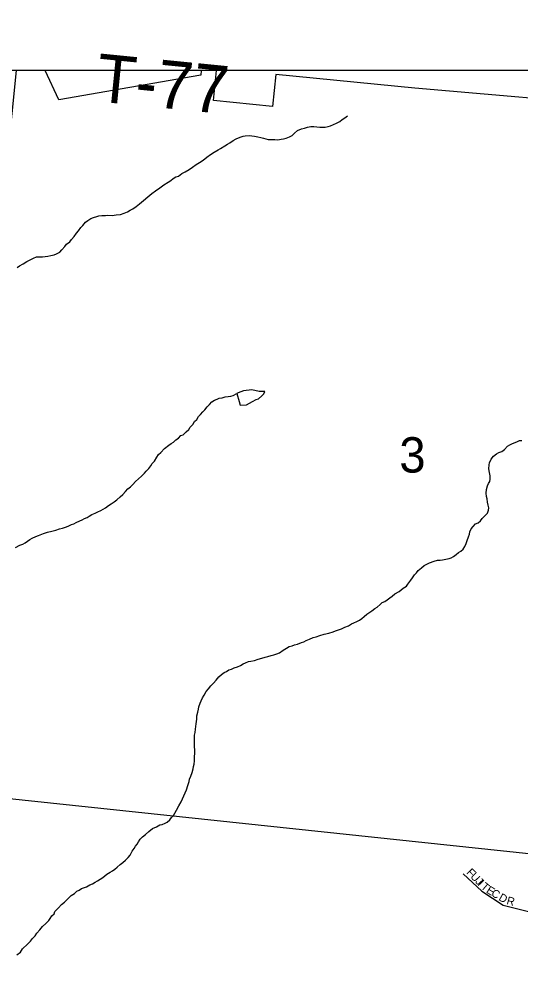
# Model space of a CAD drawing. Extents: x 0 to 34, y -4 to 22.
# Drawn here: x 5.062 to 5.48, y 18.636 to 19.435 of the extents above; entities that cross this region are included whole.
import ezdxf

# ---------------------------------------------------------------- set-up
doc = ezdxf.new("R2010")
doc.units = 0
for name, color, linetype in [('GM_X_City_Street', 7, 'Continuous'), ('GM_X_City_Street_Text', 7, 'Continuous'), ('GM_X_Corporation', 7, 'Continuous'), ('GM_X_Minor_Lake', 7, 'Continuous'), ('GM_X_Minor_River', 7, 'Continuous'), ('GM_X_Section', 7, 'Continuous'), ('GM_X_Section_Text', 7, 'Continuous'), ('GM_X_Township', 7, 'Continuous'), ('GM_X_Township_Road_Text', 7, 'Continuous'), ('SH_Text', 7, 'Continuous')]:
    doc.layers.add(name, color=color, linetype=linetype)

msp = doc.modelspace()

# ---------------------------------------------------------------- linework, layer by layer
at = {"layer": 'GM_X_City_Street'}
msp.add_lwpolyline([(5.43147, 18.72305), (5.44706, 18.70841), (5.46488, 18.69696), (5.4881, 18.69091), (5.51387, 18.68901), (5.5336, 18.68646), (5.54851, 18.68204)], dxfattribs=at)
at = {"layer": 'GM_X_Corporation'}
msp.add_lwpolyline([(5.57096, 19.36176), (5.39129, 19.37747), (5.27543, 19.38883), (5.27278, 19.3623), (5.22344, 19.36713), (5.22593, 19.39206), (5.21309, 19.39206), (5.213, 19.38827), (5.09474, 19.36784), (5.08313, 19.39206), (5.04556, 19.39206)], dxfattribs=at)
at = {"layer": 'GM_X_Minor_Lake'}
for points in [[(5.26638, 19.12474), (5.26156, 19.12486), (5.25543, 19.12607), (5.24844, 19.12544), (5.24411, 19.12367), (5.24303, 19.12316)], [(5.24303, 19.12316), (5.24474, 19.11643), (5.24574, 19.11346), (5.2511, 19.1136), (5.25599, 19.11643), (5.25898, 19.11796), (5.26087, 19.11872), (5.26387, 19.12105), (5.26553, 19.12289), (5.26638, 19.12474)]]:
    msp.add_lwpolyline(points, dxfattribs=at)
at = {"layer": 'GM_X_Minor_River'}
for points in [[(5.14901, 19.27327), (5.15173, 19.27452), (5.15418, 19.27578), (5.15637, 19.27705), (5.15911, 19.27883), (5.16186, 19.28115), (5.16517, 19.28399), (5.16875, 19.28682), (5.17205, 19.28965), (5.17508, 19.29196), (5.17865, 19.29452), (5.1822, 19.29682), (5.18576, 19.29911), (5.18796, 19.30065), (5.18988, 19.30219), (5.19207, 19.30346), (5.19423, 19.3042), (5.19698, 19.30625), (5.19998, 19.30776), (5.20326, 19.30979), (5.206, 19.31158), (5.20902, 19.31389), (5.21175, 19.31541), (5.21477, 19.31745), (5.2178, 19.32003), (5.22108, 19.32207), (5.2241, 19.32411), (5.22738, 19.32615), (5.22929, 19.32716), (5.23285, 19.32945), (5.23503, 19.33072), (5.23722, 19.33199), (5.23995, 19.33377), (5.24242, 19.3353), (5.24567, 19.33654), (5.24811, 19.33753), (5.25, 19.33774), (5.25322, 19.3379), (5.25536, 19.33784), (5.25776, 19.3375), (5.26042, 19.33688), (5.26281, 19.33627), (5.2652, 19.33566), (5.26706, 19.33534), (5.26892, 19.33475), (5.27186, 19.33466), (5.27454, 19.33458), (5.27695, 19.3345), (5.27991, 19.33494), (5.28179, 19.33515), (5.28396, 19.33589), (5.28667, 19.33687), (5.28913, 19.33813), (5.29106, 19.33994), (5.29355, 19.34227), (5.2968, 19.34351), (5.29924, 19.34423), (5.30194, 19.34495), (5.30464, 19.3454), (5.30705, 19.3456), (5.30945, 19.34525), (5.31212, 19.3449), (5.31399, 19.34485), (5.31641, 19.34504), (5.31911, 19.34549), (5.321, 19.34597), (5.32345, 19.34723), (5.32589, 19.34822), (5.32862, 19.34974), (5.33082, 19.35127), (5.33301, 19.35281), (5.33521, 19.35434)], [(5.05991, 19.22793), (5.06183, 19.22947), (5.06483, 19.23098), (5.06784, 19.23303), (5.0703, 19.23429), (5.07356, 19.23579), (5.07601, 19.23705), (5.07842, 19.23698), (5.0811, 19.23689), (5.08325, 19.2371), (5.08541, 19.23756), (5.0881, 19.23801), (5.0908, 19.23873), (5.0927, 19.23948), (5.09542, 19.24073), (5.0971, 19.24281), (5.09961, 19.24567), (5.10101, 19.2475), (5.10375, 19.24955), (5.10515, 19.25138), (5.10738, 19.25398), (5.10934, 19.25659), (5.11102, 19.25868), (5.11298, 19.26129), (5.11465, 19.26311), (5.11688, 19.26571), (5.1188, 19.26725), (5.12127, 19.26878), (5.12344, 19.26978), (5.12615, 19.2705), (5.12804, 19.27098), (5.13046, 19.27144), (5.13341, 19.27134), (5.13556, 19.27154), (5.13904, 19.27144), (5.14253, 19.27186), (5.14603, 19.27229), (5.14901, 19.27327)], [(5.05863, 18.99476), (5.06218, 18.99679), (5.06461, 18.99751), (5.06653, 18.99879), (5.06845, 19.00007), (5.07037, 19.00134), (5.07229, 19.00262), (5.07554, 19.00385), (5.07772, 19.00486), (5.08179, 19.0066), (5.08531, 19.00756), (5.08882, 19.00852), (5.09206, 19.00922), (5.09532, 19.01046), (5.09774, 19.01092), (5.101, 19.01215), (5.1029, 19.01289), (5.10507, 19.0139), (5.10724, 19.01463), (5.10915, 19.01564), (5.11214, 19.01688), (5.11405, 19.01789), (5.11596, 19.0189), (5.11813, 19.0199), (5.12004, 19.02091), (5.12223, 19.02218), (5.12495, 19.02343), (5.12712, 19.02444), (5.12958, 19.0257), (5.13149, 19.0267), (5.13339, 19.02771), (5.13614, 19.02977), (5.13833, 19.03104), (5.1408, 19.03283), (5.143, 19.03463), (5.14575, 19.03695), (5.14797, 19.03902), (5.15019, 19.04135), (5.15214, 19.0437), (5.15433, 19.04523), (5.15628, 19.04731), (5.1585, 19.04965), (5.16099, 19.05197), (5.16347, 19.0543), (5.16596, 19.05663), (5.16736, 19.05845), (5.16957, 19.06052), (5.17126, 19.06288), (5.17239, 19.06471), (5.17433, 19.06679), (5.17631, 19.06993), (5.17773, 19.07229), (5.17966, 19.07384), (5.18272, 19.07722), (5.18629, 19.08004), (5.18821, 19.08132), (5.19013, 19.0826), (5.19206, 19.08441), (5.19426, 19.08594), (5.1962, 19.08802), (5.1981, 19.08876), (5.20059, 19.09109), (5.2028, 19.09316), (5.20393, 19.09499), (5.20615, 19.09733), (5.20757, 19.09969), (5.20951, 19.1015), (5.21092, 19.10386), (5.21259, 19.10568), (5.21453, 19.10776), (5.2162, 19.10957), (5.21816, 19.11192), (5.2201, 19.114), (5.22204, 19.11607), (5.22424, 19.11761), (5.22641, 19.11834)], [(5.22641, 19.11834), (5.2283, 19.11908), (5.23073, 19.11954), (5.23317, 19.12027), (5.23558, 19.12046), (5.23801, 19.12092), (5.2399, 19.1214), (5.24303, 19.12316)], [(5.44185, 19.01446), (5.44403, 19.01546), (5.44596, 19.017), (5.44736, 19.01883), (5.44985, 19.02142), (5.4518, 19.0235), (5.45268, 19.02588), (5.45274, 19.02774), (5.45229, 19.03016), (5.45183, 19.03258), (5.45138, 19.03527), (5.45092, 19.03742), (5.45074, 19.0401), (5.45084, 19.04303), (5.45174, 19.04621), (5.45261, 19.04805), (5.45374, 19.04989), (5.45407, 19.05175), (5.45389, 19.05442), (5.45345, 19.05738), (5.45301, 19.06033), (5.45312, 19.06353), (5.45345, 19.06539), (5.45488, 19.06828), (5.45685, 19.07089), (5.45932, 19.07269), (5.46123, 19.07396), (5.46367, 19.07469), (5.46587, 19.07649), (5.46837, 19.07909), (5.47029, 19.08036), (5.47273, 19.08136), (5.47626, 19.08285), (5.47844, 19.08385), (5.48032, 19.08406)], [(5.21328, 18.8671), (5.21443, 18.86947), (5.21558, 18.87184), (5.21728, 18.87473), (5.21924, 18.87707), (5.2212, 18.87968), (5.22341, 18.88175), (5.22564, 18.88435), (5.22787, 18.88696), (5.23008, 18.88902), (5.23227, 18.89056), (5.23418, 18.89157), (5.23637, 18.89284), (5.23854, 18.89357), (5.24071, 18.89457), (5.24341, 18.89529), (5.24587, 18.89655), (5.24832, 18.89781), (5.25023, 18.89882), (5.25267, 18.89981), (5.25455, 18.90002), (5.25753, 18.90073), (5.26077, 18.9017), (5.26375, 18.90268), (5.26645, 18.9034), (5.26862, 18.90413), (5.27159, 18.90484), (5.27375, 18.90531), (5.2762, 18.9063), (5.27836, 18.90704), (5.28165, 18.90934), (5.28438, 18.91086), (5.28658, 18.91239), (5.289, 18.91285), (5.2909, 18.91359), (5.29334, 18.91432), (5.29686, 18.91555), (5.29876, 18.91629), (5.30067, 18.9173), (5.30339, 18.91855), (5.30665, 18.91979), (5.30908, 18.92051), (5.31206, 18.92149), (5.31559, 18.92272), (5.31963, 18.92339), (5.32315, 18.92462), (5.32505, 18.92536), (5.3302, 18.92707), (5.33292, 18.92832), (5.3359, 18.92957), (5.33837, 18.9311), (5.34054, 18.9321), (5.34299, 18.93309), (5.34517, 18.93436), (5.34709, 18.93564), (5.34902, 18.93745), (5.35123, 18.93925), (5.35534, 18.94206), (5.35782, 18.94412), (5.35973, 18.94513), (5.36221, 18.94719), (5.36414, 18.949), (5.36631, 18.94974), (5.36823, 18.95128), (5.37043, 18.95281), (5.37235, 18.95436), (5.37456, 18.95616), (5.37811, 18.95819), (5.38142, 18.96102), (5.38415, 18.96254), (5.38528, 18.96438), (5.38779, 18.9675), (5.3892, 18.9696), (5.39089, 18.97195), (5.39255, 18.97377), (5.39395, 18.9756), (5.39671, 18.97792), (5.39891, 18.97972), (5.4011, 18.98099), (5.40354, 18.98198), (5.40734, 18.98346), (5.41004, 18.98418), (5.41246, 18.98437), (5.41434, 18.98458), (5.41704, 18.98503), (5.41974, 18.98575), (5.42163, 18.98623), (5.42354, 18.98724), (5.42574, 18.98904), (5.42767, 18.99058), (5.42959, 18.99186), (5.43151, 18.9934), (5.43293, 18.99576), (5.43408, 18.99813), (5.43496, 19.00051), (5.43587, 19.00369), (5.43675, 19.0058), (5.43708, 19.00792), (5.43823, 19.01029), (5.43991, 19.01238), (5.44185, 19.01446)], [(5.05974, 18.65546), (5.06276, 18.65777), (5.06446, 18.66039), (5.0686, 18.66427), (5.0711, 18.66686), (5.07278, 18.66895), (5.075, 18.67128), (5.07642, 18.67365), (5.07891, 18.67624), (5.08115, 18.67911), (5.08392, 18.6817), (5.0864, 18.68402), (5.08754, 18.68586), (5.08868, 18.68796), (5.09061, 18.68977), (5.09121, 18.69162), (5.09426, 18.69473), (5.09675, 18.69733), (5.09923, 18.69939), (5.10201, 18.70224), (5.10504, 18.70482), (5.10778, 18.7066), (5.10971, 18.70841), (5.11162, 18.70942), (5.11354, 18.7107), (5.11761, 18.71218), (5.12034, 18.7137), (5.12278, 18.71469), (5.12497, 18.71596), (5.12688, 18.71723), (5.12907, 18.7185), (5.13125, 18.71977), (5.13456, 18.72261), (5.1373, 18.72439), (5.13921, 18.7254), (5.1414, 18.72694), (5.14333, 18.72848), (5.14582, 18.73081), (5.14801, 18.73234), (5.15022, 18.73441), (5.15243, 18.73648), (5.15411, 18.73857), (5.15582, 18.74172), (5.15751, 18.74407), (5.15864, 18.74591), (5.15977, 18.74774), (5.16091, 18.74958), (5.16232, 18.75194), (5.16426, 18.75375), (5.16674, 18.75581), (5.16949, 18.75813), (5.17279, 18.7607), (5.17606, 18.7622), (5.17879, 18.76372), (5.18068, 18.76419), (5.18312, 18.76519), (5.18502, 18.76593), (5.18697, 18.768), (5.18837, 18.76983), (5.19003, 18.77165), (5.19117, 18.77349), (5.19259, 18.77611), (5.19458, 18.77952), (5.19657, 18.78294), (5.19772, 18.78531), (5.19888, 18.78794), (5.19976, 18.79032), (5.20092, 18.79295), (5.20211, 18.79666), (5.20329, 18.79983), (5.20362, 18.80169), (5.20451, 18.80433), (5.20569, 18.8075), (5.20658, 18.81041), (5.20691, 18.81227), (5.20725, 18.8144), (5.20761, 18.81706), (5.20772, 18.82053), (5.20782, 18.82346), (5.20791, 18.82613), (5.20773, 18.82881), (5.20755, 18.83148), (5.20764, 18.83415), (5.20771, 18.83629), (5.20778, 18.83842), (5.20813, 18.84082), (5.20848, 18.84348), (5.20882, 18.8456), (5.20917, 18.848), (5.20923, 18.84986), (5.20956, 18.85172), (5.20965, 18.85466), (5.21055, 18.85757), (5.21091, 18.86023), (5.21124, 18.86209), (5.21241, 18.86499), (5.21328, 18.8671)]]:
    msp.add_lwpolyline(points, dxfattribs=at)
at = {"layer": 'GM_X_Section'}
for points in [[(5.05898, 19.39206), (4.99815, 18.79148), (5.71418, 18.71571), (5.78137, 19.37167), (5.57772, 19.39206)], [(4.99815, 18.79148), (5.71418, 18.71571), (5.63665, 17.94928), (4.91493, 18.01957), (4.99198, 18.73294)]]:
    msp.add_lwpolyline(points, close=True, dxfattribs=at)
at = {"layer": 'GM_X_Township'}
msp.add_lwpolyline([(7.89749, 19.16191), (6.95864, 19.25607), (6.91699, 19.26013), (6.84651, 19.26789), (6.43484, 19.30717), (5.93867, 19.35552), (5.77684, 19.3713), (5.56398, 19.39206), (3.94357, 19.39206), (3.94357, 19.55014)], dxfattribs=at)
at = {"layer": 'SH_Text'}
msp.add_lwpolyline([(3.94357, 19.84879), (6.22504, 19.84879), (6.22504, 19.39206), (3.94357, 19.39206)], close=True, dxfattribs=at)

# ---------------------------------------------------------------- texts
at = {"layer": 'GM_X_City_Street_Text'}
for s, rotation, p in [('F', 313.97594, (5.43377, 18.72365)), ('U', 313.96456, (5.43703, 18.72028)), ('J', 313.96104, (5.4411, 18.71605)), ('I', 313.94939, (5.44314, 18.71394)), ('T', 319.68976, (5.4457, 18.71133)), ('E', 328.19961, (5.45016, 18.70766)), ('C', 328.73681, (5.4542, 18.70515)), ('D', 331.19423, (5.46049, 18.70133)), ('R', 344.7369, (5.46723, 18.69786))]:
    msp.add_text(s, height=0.00667, rotation=rotation, dxfattribs=at).set_placement(p)
at = {"layer": 'GM_X_Section_Text'}
msp.add_text('3', height=0.02944, rotation=0.00001, dxfattribs=at).set_placement((5.3783, 19.05723))
at = {"layer": 'GM_X_Township_Road_Text'}
msp.add_text('T-77', height=0.04, rotation=354.32503, dxfattribs=at).set_placement((5.12451, 19.36658))

doc.saveas('drawing.dxf')
